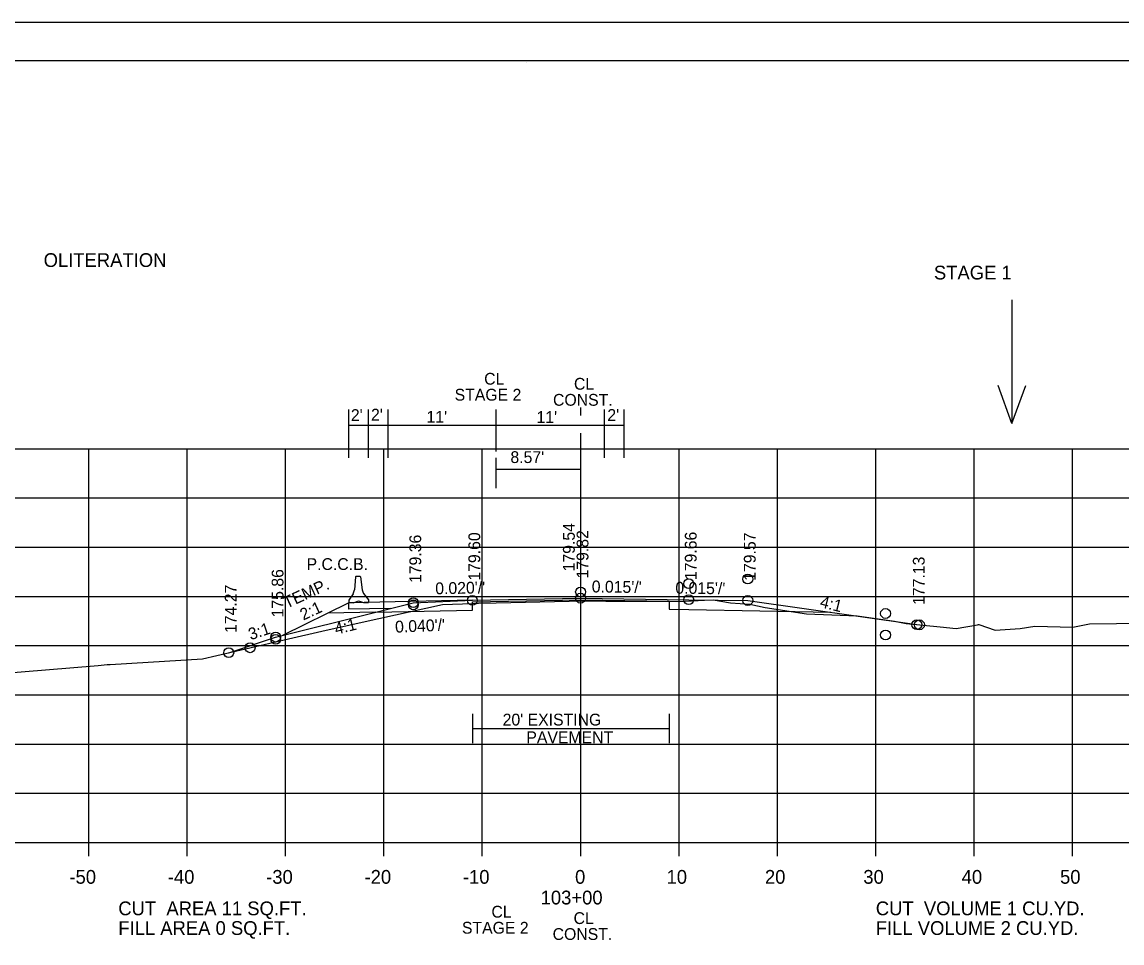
# Model space of a CAD drawing. Extents: x 915787 to 919910, y 133456 to 136717.
# Drawn here: x 916357.2 to 916469, y 133575.8 to 133669.4 of the extents above; entities that cross this region are included whole.
import ezdxf

# ---------------------------------------------------------------- set-up
doc = ezdxf.new("R2010")
doc.units = 0
for name, color, linetype in [('R_Axis', 7, 'Continuous'), ('R_Axis Annot', 7, 'Continuous'), ('R_Border', 7, 'Continuous'), ('R_Border Notes', 7, 'Continuous'), ('R_Exist Surface', 7, 'Continuous'), ('R_Exist Surface Annot', 7, 'Continuous'), ('R_Fin Surface', 7, 'Continuous'), ('R_Grid', 7, 'Continuous'), ('R_MOT', 7, 'Continuous'), ('R_No Plot', 7, 'Continuous'), ('R_Water Annot', 7, 'Continuous'), ('R_Xsect Elev', 7, 'Continuous'), ('R_Xsect Slope', 7, 'Continuous')]:
    doc.layers.add(name, color=color, linetype=linetype)

msp = doc.modelspace()

# ---------------------------------------------------------------- linework, layer by layer
at = {"layer": 'R_Axis'}
for p, q in [((916273.98, 133586.01), (916553.98, 133586.01)), ((916363.98, 133584.61), (916363.98, 133586.01)), ((916373.98, 133584.61), (916373.98, 133586.01)), ((916383.98, 133584.61), (916383.98, 133586.01)), ((916393.98, 133584.61), (916393.98, 133586.01)), ((916403.98, 133584.61), (916403.98, 133586.01)), ((916413.98, 133584.61), (916413.98, 133586.01)), ((916423.98, 133584.61), (916423.98, 133586.01)), ((916433.98, 133584.61), (916433.98, 133586.01)), ((916443.98, 133584.61), (916443.98, 133586.01)), ((916453.98, 133584.61), (916453.98, 133586.01)), ((916463.98, 133584.61), (916463.98, 133586.01))]:
    msp.add_line(p, q, dxfattribs=at)
at = {"layer": 'R_Border'}
for p, q in [((916255.98, 133665.47), (916572.16, 133665.47)), ((916408.5, 133665.21), (916408.5, 133665.21)), ((916408.5, 133665.21), (916408.5, 133665.21))]:
    msp.add_line(p, q, dxfattribs=at)
at = {"layer": 'R_Border Notes'}
for p, q in [((916413.98, 133629.4), (916413.98, 133630.2)), ((916413.98, 133622.02), (916413.98, 133627.6)), ((916405.4, 133622.02), (916405.4, 133625.1)), ((916405.41, 133623.92), (916413.98, 133623.92))]:
    msp.add_line(p, q, dxfattribs=at)
at = {"layer": 'R_Exist Surface'}
msp.add_lwpolyline([(916352.13, 133602.95), (916364.93, 133604), (916365.86, 133604.08), (916366.14, 133604.1), (916375.54, 133604.67), (916384.29, 133606.69), (916387.68, 133607.47), (916391.76, 133608.38), (916399.93, 133610.2), (916402.97, 133610.3), (916403.59, 133610.33), (916405.4, 133610.37), (916414.29, 133610.56), (916416.53, 133610.54), (916423.97, 133610.49), (916426.56, 133610.62), (916427.44, 133610.67), (916429.21, 133610.36), (916431.17, 133610.22), (916432.73, 133609.88), (916436.95, 133609.25), (916442.1, 133609.05), (916445.88, 133608.5), (916447.07, 133608.26), (916450.52, 133607.9), (916452.16, 133607.75), (916454.31, 133608.13), (916454.43, 133608.14), (916454.45, 133608.14), (916454.46, 133608.14), (916456.1, 133607.57), (916458.65, 133607.74), (916460.16, 133607.98), (916464.02, 133607.89), (916465.72, 133608.23), (916476.68, 133608.34)], dxfattribs=at)
at = {"layer": 'R_Exist Surface Annot'}
for p, q in [((916402.98, 133599.09), (916402.98, 133596.09)), ((916422.98, 133599.09), (916422.98, 133596.09)), ((916402.98, 133597.59), (916422.98, 133597.59))]:
    msp.add_line(p, q, dxfattribs=at)
at = {"layer": 'R_Fin Surface'}
for points in [[(916378.21, 133605.29), (916382.97, 133606.87), (916393.16, 133609.42), (916396.97, 133610.37), (916402.97, 133610.61), (916413.97, 133610.83), (916424.97, 133610.67), (916430.97, 133610.59), (916448.15, 133608.14)], [(916393.16, 133609.42), (916402.98, 133609.62), (916402.97, 133610.45), (916413.97, 133610.67), (916422.97, 133610.54), (916422.98, 133609.7), (916424.98, 133609.67), (916439.42, 133609.39)]]:
    msp.add_lwpolyline(points, dxfattribs=at)
at = {"layer": 'R_Grid'}
for p, q in [((916273.98, 133626.01), (916553.98, 133626.01)), ((916363.98, 133586.01), (916363.98, 133626.01)), ((916373.98, 133586.01), (916373.98, 133626.01)), ((916383.98, 133586.01), (916383.98, 133626.01)), ((916393.98, 133586.01), (916393.98, 133626.01)), ((916403.98, 133586.01), (916403.98, 133626.01)), ((916413.98, 133586.01), (916413.98, 133626.01)), ((916423.98, 133586.01), (916423.98, 133626.01)), ((916433.98, 133586.01), (916433.98, 133626.01)), ((916443.98, 133586.01), (916443.98, 133626.01)), ((916453.98, 133586.01), (916453.98, 133626.01)), ((916463.98, 133586.01), (916463.98, 133626.01)), ((916273.98, 133621.01), (916553.98, 133621.01)), ((916273.98, 133616.01), (916553.98, 133616.01)), ((916273.98, 133611.01), (916553.98, 133611.01)), ((916273.98, 133606.01), (916553.98, 133606.01)), ((916273.98, 133601.01), (916553.98, 133601.01)), ((916273.98, 133596.01), (916553.98, 133596.01)), ((916273.98, 133591.01), (916553.98, 133591.01)), ((916273.98, 133586.01), (916553.98, 133586.01))]:
    msp.add_line(p, q, dxfattribs=at)
at = {"layer": 'R_MOT'}
for p, q in [((916391.09, 133612.98), (916390.98, 133611.67)), ((916391.09, 133612.98), (916391.16, 133613.05)), ((916391.16, 133613.05), (916391.53, 133613.05)), ((916391.53, 133613.05), (916391.6, 133612.99)), ((916391.6, 133612.99), (916391.77, 133611.69)), ((916390.84, 133611.28), (916390.4, 133610.61)), ((916391.92, 133611.3), (916392.4, 133610.65)), ((916390.4, 133610.61), (916390.4, 133610.36)), ((916390.9, 133610.37), (916390.4, 133610.36)), ((916390.9, 133610.37), (916391.4, 133610.55)), ((916391.4, 133610.55), (916391.9, 133610.39)), ((916391.9, 133610.39), (916392.4, 133610.4)), ((916392.4, 133610.65), (916392.4, 133610.4))]:
    msp.add_line(p, q, dxfattribs=at)
for centre, start, end in [((916390.15, 133611.74), 326.1785, 355.1615), ((916392.6, 133611.79), 187.1795, 216.1625)]:
    msp.add_arc(centre, 0.833, start, end, dxfattribs=at)
at = {"layer": 'R_No Plot'}
msp.add_line((916243.57, 133669.37), (916576.91, 133669.37), dxfattribs=at)
for points in [[(916243.57, 133669.37), (916576.91, 133669.37), (916576.91, 133456.03), (916243.57, 133456.03)], [(916489.9, 133665.47), (916489.9, 133655.59), (916525.63, 133655.59), (916525.63, 133652.67), (916548.83, 133652.67), (916548.83, 133629.46), (916572.16, 133629.46), (916572.16, 133460.01), (916255.98, 133460.01), (916255.98, 133665.47)]]:
    msp.add_lwpolyline(points, close=True, dxfattribs=at)
for centre in [(916430.97, 133612.77), (916424.97, 133612.3), (916402.97, 133610.61), (916402.97, 133610.61), (916413.97, 133611.46), (916413.97, 133610.83), (916424.97, 133610.67), (916430.97, 133610.59), (916396.97, 133610.37), (916396.97, 133610.15), (916444.97, 133609.27), (916448.15, 133608.14), (916448.42, 133608.12), (916382.97, 133606.87), (916382.97, 133606.65), (916444.97, 133607.09), (916378.21, 133605.29), (916380.38, 133605.79)]:
    msp.add_circle(centre, 0.5, dxfattribs=at)
at = {"layer": 'R_Water Annot'}
for p, q in [((916457.82, 133641.14), (916457.82, 133628.57)), ((916457.82, 133628.57), (916456.42, 133632.42)), ((916457.82, 133628.57), (916459.22, 133632.42))]:
    msp.add_line(p, q, dxfattribs=at)
at = {"layer": 'R_Xsect Slope'}
for p, q in [((916390.4, 133625.1), (916390.4, 133630.01)), ((916392.4, 133625.1), (916392.4, 133630.01)), ((916394.4, 133625.1), (916394.4, 133630.01)), ((916405.4, 133625.72), (916405.4, 133630.01)), ((916416.4, 133625.1), (916416.4, 133630.01)), ((916418.4, 133625.1), (916418.4, 133630.01)), ((916390.4, 133628.39), (916418.4, 133628.39)), ((916390.4, 133610.36), (916383.68, 133607.05)), ((916402.97, 133610.61), (916390.4, 133610.36)), ((916393.16, 133609.42), (916388.29, 133609.32))]:
    msp.add_line(p, q, dxfattribs=at)
msp.add_lwpolyline([(916394.6, 133609.78), (916390.42, 133609.7), (916390.4, 133610.36)], dxfattribs=at)

# ---------------------------------------------------------------- texts
at = {"layer": 'R_Axis Annot'}
for s, p in [('-50', (916362.01, 133581.81)), ('-40', (916372.01, 133581.81)), ('-30', (916382.01, 133581.81)), ('-20', (916392.01, 133581.81)), ('-10', (916402.01, 133581.81)), ('0', (916413.41, 133581.81)), ('10', (916422.71, 133581.81)), ('20', (916432.71, 133581.81)), ('30', (916442.71, 133581.81)), ('40', (916452.71, 133581.81)), ('50', (916462.71, 133581.81)), ('103+00', (916409.91, 133579.71))]:
    msp.add_text(s, height=1.4, dxfattribs=at).set_placement(p)
at = {"layer": 'R_Border Notes'}
for s, height, p in [('OLITERATION', 1.4, (916359.39, 133644.48)), ('STAGE 1', 1.4, (916449.89, 133643.21)), ('CL', 1.2, (916404.17, 133632.52)), ('CL', 1.2, (916413.3, 133632.01)), ('STAGE 2', 1.2, (916401.17, 133630.9)), ('CONST.', 1.2, (916411.17, 133630.38)), ("8.57'", 1.2, (916406.84, 133624.56)), ('CUT  AREA 11 SQ.FT.', 1.4, (916366.98, 133578.61)), ('CUT  VOLUME 1 CU.YD.', 1.4, (916443.98, 133578.61)), ('CL', 1.2, (916404.91, 133578.37)), ('CL', 1.2, (916413.26, 133577.72)), ('FILL AREA 0 SQ.FT.', 1.4, (916366.98, 133576.61)), ('STAGE 2', 1.2, (916401.91, 133576.74)), ('FILL VOLUME 2 CU.YD.', 1.4, (916443.98, 133576.61)), ('CONST.', 1.2, (916411.13, 133576.1))]:
    msp.add_text(s, height=height, dxfattribs=at).set_placement(p)
at = {"layer": 'R_Exist Surface Annot'}
for s, p in [("20' EXISTING", (916406.05, 133597.89)), ('PAVEMENT', (916408.46, 133596.09))]:
    msp.add_text(s, height=1.2, dxfattribs=at).set_placement(p)
at = {"layer": 'R_MOT'}
msp.add_text('DWB 1-14-10', height=0.004, rotation=91.1705, dxfattribs=at).set_placement((916390.41, 133610.37))
at = {"layer": 'R_Xsect Elev'}
for s, p in [('179.54', (916413.38, 133613.55)), ('179.36', (916397.77, 133612.37)), ('179.60', (916403.77, 133612.61)), ('179.82', (916414.77, 133612.83)), ('179.66', (916425.77, 133612.67)), ('179.57', (916431.77, 133612.59)), ('177.13', (916448.95, 133610.14)), ('175.86', (916383.77, 133608.87)), ('174.27', (916379.01, 133607.29))]:
    msp.add_text(s, height=1.2, rotation=90, dxfattribs=at).set_placement(p)
at = {"layer": 'R_Xsect Slope'}
for s, p in [("2'", (916390.62, 133628.83)), ("2'", (916392.67, 133628.87)), ("2'", (916416.69, 133628.84)), ("11'", (916398.31, 133628.66)), ("11'", (916409.49, 133628.63)), ('P.C.C.B.', (916386.12, 133613.69))]:
    msp.add_text(s, height=1.2, dxfattribs=at).set_placement(p)
for s, rotation, p in [('TEMP.', 24.829, (916384.1, 133609.75)), ("0.020'/'", 1.1458, (916399.21, 133611.22)), ("0.015'/'", 359.1686, (916415.1, 133611.42)), ("0.015'/'", 359.1686, (916423.6, 133611.29)), ('2:1', 24.829, (916385.78, 133608.54)), ('4:1', 345.9638, (916438.23, 133609.93)), ("0.040'/'", 2.2906, (916395.14, 133607.32)), ('3:1', 18.4349, (916380.43, 133606.55)), ('4:1', 14.0362, (916389.12, 133607.11))]:
    msp.add_text(s, height=1.2, rotation=rotation, dxfattribs=at).set_placement(p)

doc.saveas('drawing.dxf')
